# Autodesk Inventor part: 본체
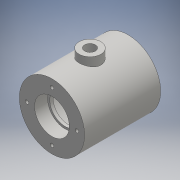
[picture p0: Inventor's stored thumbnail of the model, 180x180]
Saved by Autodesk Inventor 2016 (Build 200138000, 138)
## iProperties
Created: 2018-12
Part Number: 본체
Material: 일반
Document SubType Name: Modeling
Designer: USER
Density: 1 g/cm^3
Appearance: 기본값
Author: USER
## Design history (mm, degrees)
sketch "스케치1"
  geometry: C1 r 30 at (0, 75); 1 further point
  constraints: 1 centre point, 1 vertical alignment
  dimensions: "d0" = 60 diameter of C1; "d1" = 75 distance of point (0, 0) C1.centre
extrude "돌출1" new body sketch "스케치1" distance "d2" = 70; taper "d3" = 0 deg
sketch "스케치2"
  geometry: L1 (0, 105)-(0, 45) reference; L2 (0, 75)-(70, 75); L3 (70, 45)-(70, 105) reference; L4 (0, 75)-(0, 91); L5 (0, 91)-(12, 91); L6 (12, 91)-(12, 89); L7 (12, 89)-(15, 89); L8 (15, 89)-(15, 100); L9 (15, 100)-(55, 100); L10 (55, 100)-(55, 89); L11 (55, 89)-(58, 89); L12 (58, 89)-(58, 91); L13 (58, 91)-(70, 91); L14 (70, 91)-(70, 75); 1 further point
  constraints: 24 end point, 6 perpendicular, 2 midpoint, 2 point on line, 1 collinear, 1 parallel, 1 vertical
  dimensions: "d4" = 16 distance of L2.start L4.end; "d5" = 12 distance of L4.end L5.end; "d6" = 2 distance of L5.end L6.end; "d7" = 3 distance of L6.end L7.end; "d8" = 11 distance of L7.end L8.end; "d9" = 40 distance of L8.end L9.end; "d10" = 11 distance of L9.end L10.end; "d11" = 3 distance of L10.end L11.end; "d12" = 2 distance of L11.end L12.end; "d13" = 12 distance of L12.end L13.end
revolve "회전1" sketch "스케치2" stored, may be unused: angle "d14" = 90 deg
node "작업 평면1"
sketch "스케치3"
  geometry: C1 r 10 at (0, 35); 1 further point
  constraints: 1 centre point, 1 vertical alignment
  dimensions: "d16" = 20 diameter of C1; "d17" = 35 distance of point (0, 0) C1.centre
extrude "돌출2" join sketch "스케치3" stored distance "d18" = 70; taper "d19" = 0 deg
sketch "스케치4"
  geometry: C1 r 10 at (0, 0) reference; C2 r 5 at (0, 0); 1 further point
  constraints: 1 centre point, 1 coincident
  dimensions: "d20" = 10 diameter of C2
extrude "돌출3" cut sketch "스케치4" stored distance "d21" = 70; taper "d22" = 0 deg; dims "d10" = 11
sketch "스케치5"
  geometry: C1 r 16 at (0, 0) reference; C2 r 30 at (0, 0) reference; 2 further points
  constraints: 1 vertical alignment
  dimensions: "d23" = 23 distance of point (0, 23) C1.centre
hole "구멍1" sketch "스케치5" at (0, 23) diameter "d24" = 3.242; stored, may be unused: countersink angle "d28" = 90 deg, drill point angle "d30" = 118 deg; dims "d25" = 8, "d26" = 4, "d27" = 2, "d29" = 10
node "작업 평면2"
node "솔리드1"
pattern_circular "원형 패턴1" dims angle "d32" = 360 deg
mirror "대칭1"
node "투영된 루프1"
node "투영된 루프2"
other parameters: "d15" = 112, "d34" = -35
